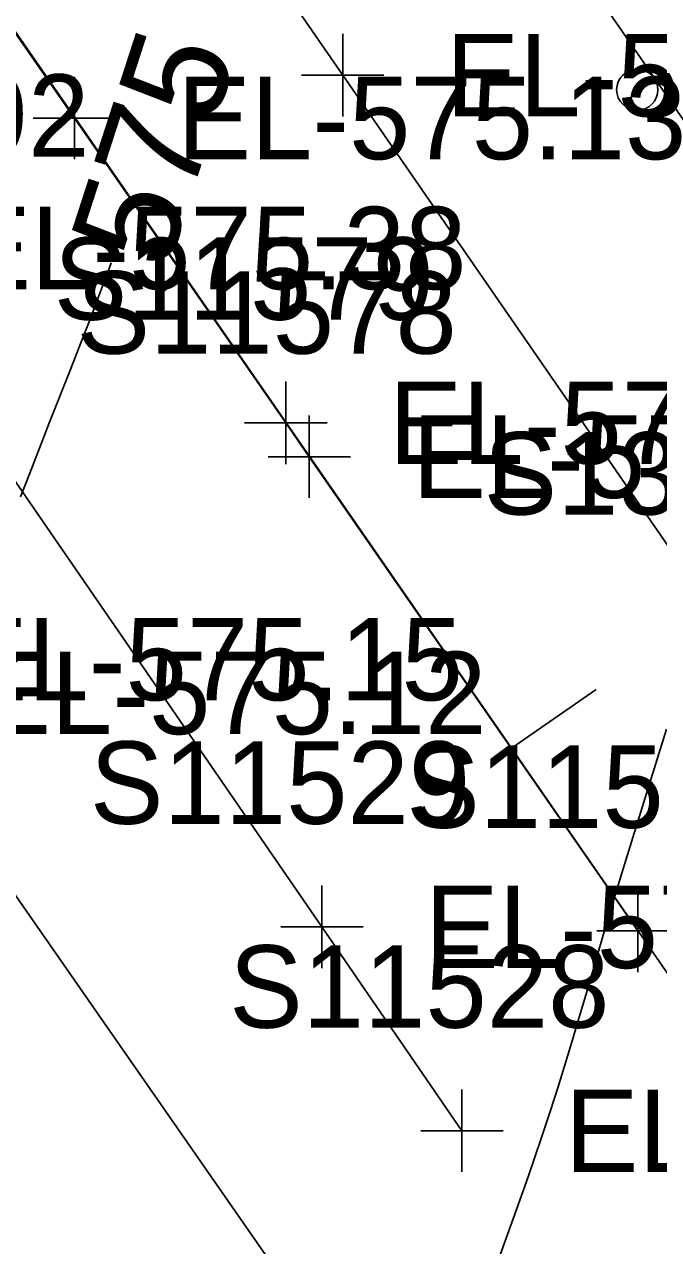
# Model space of a CAD drawing. Extents: x 1729869 to 1735532, y 648588 to 653771.
# Drawn here: x 1732050 to 1732080.7, y 650776.1 to 650835.3 of the extents above; entities that cross this region are included whole.
import ezdxf

# ---------------------------------------------------------------- set-up
doc = ezdxf.new("R2010")
doc.units = 0
for name, color, linetype in [('SURVEY - CENTERLINE - Preliminary', 7, 'Continuous'), ('SURVEY - CENTERLINE - Preliminary Text', 7, 'Continuous'), ('SURVEY - CONTOURS - Index with Text', 7, 'Continuous'), ('SURVEY - CONTOURS - Intermediate with optional Text', 7, 'Continuous'), ('SURVEY - DTM - Spot Points - Locators', 7, 'Continuous'), ('SURVEY - TRAFFIC CONTROL - Pavement Marking - Points - Elevations', 7, 'Continuous'), ('SURVEY - TRAFFIC CONTROL - Pavement Marking - Points - Locators', 7, 'Continuous'), ('SURVEY - TRAFFIC CONTROL - Pavement Marking - Points - Numbers', 7, 'Continuous'), ('SURVEY - TRAFFIC CONTROL - Pavement Marking with Text', 7, 'Continuous'), ('SURVEY - TRANSPORTATION - Features', 7, 'Continuous'), ('SURVEY - TRANSPORTATION - Roads', 7, 'Continuous'), ('SURVEY - TRANSPORTATION - Roads - Points - Elevations', 7, 'Continuous'), ('SURVEY - TRANSPORTATION - Roads - Points - Locators', 7, 'Continuous'), ('SURVEY - TRANSPORTATION - Roads - Points - Numbers', 7, 'Continuous')]:
    doc.layers.add(name, color=color, linetype=linetype)

msp = doc.modelspace()

# ---------------------------------------------------------------- linework, layer by layer
at = {"layer": 'SURVEY - CENTERLINE - Preliminary'}
msp.add_line((1731973.859, 650944.286), (1732084.595, 650784.278), dxfattribs=at)
at = {"layer": 'SURVEY - CENTERLINE - Preliminary Text'}
msp.add_line((1732073.579, 650800.196), (1732077.69, 650803.042), dxfattribs=at)
at = {"layer": 'SURVEY - CONTOURS - Index with Text'}
msp.add_lwpolyline([(1732054.171, 650823.748), (1732053.986, 650823.246), (1732053.575, 650822.145), (1732053.146, 650821.014), (1732052.702, 650819.86), (1732052.198, 650818.574), (1732051.18, 650816.007), (1732050.686, 650814.755), (1732050.214, 650813.544), (1732049.775, 650812.389)], dxfattribs=at)
at = {"layer": 'SURVEY - CONTOURS - Intermediate with optional Text'}
msp.add_lwpolyline([(1732081.093, 650801.11), (1732079.467, 650795.862), (1732078.937, 650794.131), (1732078.438, 650792.481), (1732078.001, 650791.004), (1732077.187, 650788.212), (1732076.871, 650787.136), (1732076.545, 650786.041), (1732076.204, 650784.918), (1732075.844, 650783.76), (1732075.459, 650782.559), (1732075.046, 650781.306), (1732074.39, 650779.39), (1732073.685, 650777.4), (1732072.951, 650775.39)], dxfattribs=at)
at = {"layer": 'SURVEY - DTM - Spot Points - Locators'}
msp.add_circle((1732079.683, 650832.143), 1, dxfattribs=at)
at = {"layer": 'SURVEY - TRAFFIC CONTROL - Pavement Marking - Points - Locators'}
for p, q in [((1732052.381, 650832.771), (1732052.381, 650828.771)), ((1732054.381, 650830.771), (1732050.381, 650830.771)), ((1732062.635, 650817.982), (1732062.635, 650813.982)), ((1732063.774, 650816.338), (1732063.774, 650812.338)), ((1732064.635, 650815.982), (1732060.635, 650815.982)), ((1732065.774, 650814.338), (1732061.774, 650814.338)), ((1732064.391, 650793.523), (1732064.391, 650789.523)), ((1732079.716, 650793.328), (1732079.716, 650789.328)), ((1732066.391, 650791.523), (1732062.391, 650791.523)), ((1732081.716, 650791.328), (1732077.716, 650791.328)), ((1732071.178, 650783.63), (1732071.178, 650779.63)), ((1732073.178, 650781.63), (1732069.178, 650781.63))]:
    msp.add_line(p, q, dxfattribs=at)
at = {"layer": 'SURVEY - TRAFFIC CONTROL - Pavement Marking with Text'}
for points in [[(1732071.178, 650781.63), (1732064.391, 650791.523), (1732041.716, 650824.464), (1732030.286, 650840.871), (1732015.488, 650862.243), (1732003.065, 650880.396), (1731991.722, 650896.865), (1731961.055, 650941.304), (1731940.66, 650970.964), (1731935.004, 650979.209), (1731932.728, 650982.499), (1731929.311, 650987.429), (1731912.222, 651012.084), (1731906.535, 651020.309), (1731905.401, 651021.955), (1731901.996, 651026.895), (1731896.322, 651035.129), (1731878.125, 651061.45), (1731857.644, 651091.055), (1731837.261, 651120.728)], [(1732079.716, 650791.328), (1732063.774, 650814.338), (1732062.635, 650815.982), (1732052.381, 650830.771), (1732039.833, 650848.837), (1732030.709, 650861.975), (1732013.727, 650886.702), (1732012.591, 650888.347), (1732003.481, 650901.498), (1731993.232, 650916.293), (1731971.594, 650947.525), (1731957.986, 650967.289), (1731947.969, 650982.065)]]:
    msp.add_lwpolyline(points, dxfattribs=at)
at = {"layer": 'SURVEY - TRANSPORTATION - Features'}
msp.add_lwpolyline([(1731968.374, 650998.805), (1731968.232, 650997.903), (1731968.308, 650996.747), (1731968.923, 650995.273), (1731987.082, 650968.094), (1732015.503, 650926.959), (1732043.863, 650885.836), (1732072.262, 650844.669), (1732100.659, 650803.577)], dxfattribs=at)
at = {"layer": 'SURVEY - TRANSPORTATION - Roads'}
for points in [[(1732070.093, 650763.484), (1732042.682, 650802.875), (1732041.54, 650804.516), (1732023.428, 650830.889), (1731999.56, 650865.439), (1731970.027, 650908.23), (1731954.156, 650931.293), (1731943.93, 650946.103), (1731925.721, 650972.412), (1731901.866, 651006.976), (1731875.733, 651044.828), (1731857.557, 651071.165), (1731837.153, 651100.823), (1731829.218, 651112.356), (1731814.383, 651133.708), (1731800.811, 651153.502), (1731787.281, 651173.325), (1731777.063, 651188.144), (1731750.84, 651225.938), (1731731.609, 651253.978), (1731715.775, 651277.072), (1731695.363, 651306.729), (1731670.421, 651342.978)], [(1731866.856, 651135.373), (1731893.09, 651092.809), (1731909.859, 651065.556), (1731920.319, 651048.509), (1731940.263, 651016.166), (1731949.77, 651000.883), (1731962.084, 650982.655), (1731974.516, 650964.508), (1731985.875, 650948.049), (1731988.138, 650944.751), (1732026.696, 650888.752), (1732054.033, 650849.307), (1732065.396, 650832.853), (1732083.577, 650806.529), (1732093.848, 650791.753), (1732098.884, 650784.51)]]:
    msp.add_lwpolyline(points, dxfattribs=at)
at = {"layer": 'SURVEY - TRANSPORTATION - Roads - Points - Locators'}
for p, q in [((1732065.396, 650834.853), (1732065.396, 650830.853)), ((1732067.396, 650832.853), (1732063.396, 650832.853))]:
    msp.add_line(p, q, dxfattribs=at)

# ---------------------------------------------------------------- texts
at = {"layer": 'SURVEY - CONTOURS - Index with Text'}
msp.add_text('575', height=5, rotation=72.04405, dxfattribs=at).set_placement((1732056.852, 650823.269))
at = {"layer": 'SURVEY - TRAFFIC CONTROL - Pavement Marking - Points - Elevations'}
for s, p in [('EL-575.13', (1732057.381, 650828.771)), ('EL-575.38', (1732046.716, 650822.464)), ('EL-574.67', (1732067.635, 650813.982)), ('EL-574.64', (1732068.774, 650812.338)), ('EL-574.40', (1732069.391, 650789.523)), ('EL-574.13', (1732076.178, 650779.63))]:
    msp.add_text(s, height=4, dxfattribs=at).set_placement(p)
at = {"layer": 'SURVEY - TRAFFIC CONTROL - Pavement Marking - Points - Numbers'}
for s, p in [('S11579', (1732051.38, 650820.982)), ('S11578', (1732052.487, 650819.338)), ('S11529', (1732053.136, 650796.523)), ('S11577', (1732068.476, 650796.328)), ('S11528', (1732059.891, 650786.63))]:
    msp.add_text(s, height=4, dxfattribs=at).set_placement(p)
at = {"layer": 'SURVEY - TRANSPORTATION - Roads - Points - Elevations'}
for s, p in [('EL-574.76', (1732070.396, 650830.853)), ('EL-575.92', (1732028.428, 650828.889)), ('EL-575.15', (1732046.54, 650802.516)), ('EL-575.12', (1732047.682, 650800.875))]:
    msp.add_text(s, height=4, dxfattribs=at).set_placement(p)
at = {"layer": 'SURVEY - TRANSPORTATION - Roads - Points - Numbers'}
msp.add_text('S13016', height=4, dxfattribs=at).set_placement((1732072.227, 650811.529))

doc.saveas('drawing.dxf')
